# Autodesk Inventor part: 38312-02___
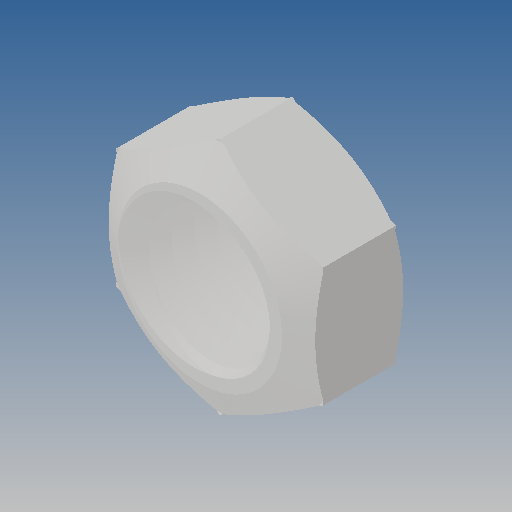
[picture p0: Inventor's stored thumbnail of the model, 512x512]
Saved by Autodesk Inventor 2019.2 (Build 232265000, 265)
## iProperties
Created: 2010-06
Part Number: 38312-02___
Material: Ogólny
Document SubType Name: Modeling
Designer: CADENGINEERING4
Density: 1 g/cm^3
Appearance: Domyślna
Author: CADENGINEERING4
Revision Number: ANY
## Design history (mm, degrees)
feature "NONE"
node "Bryła1"
